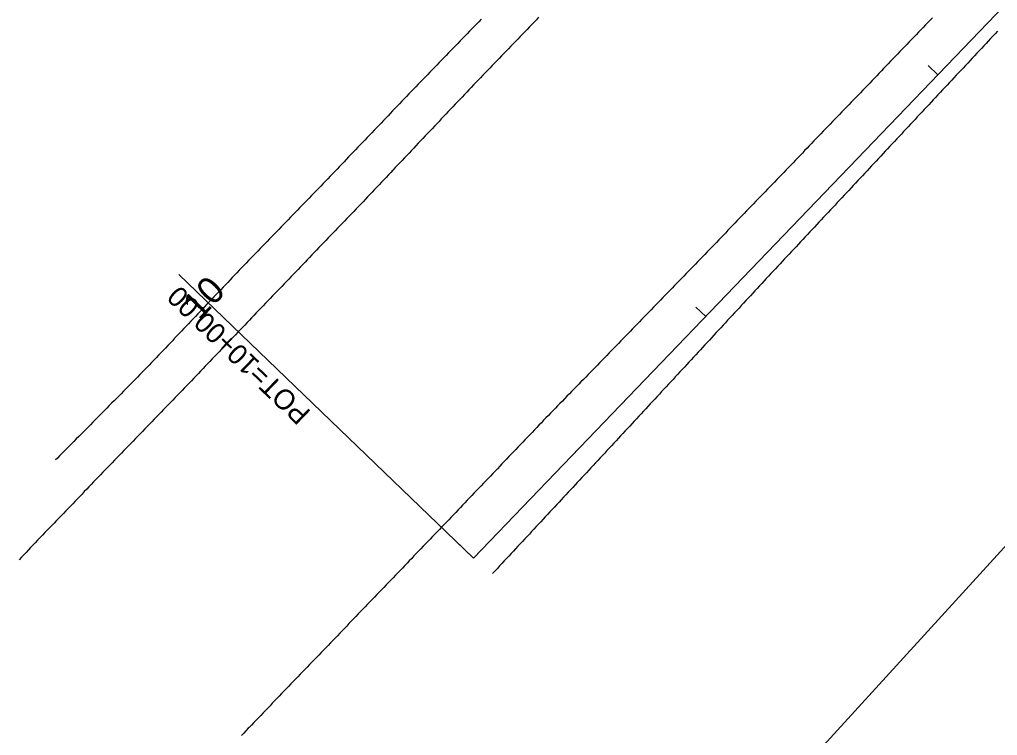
# Model space of a CAD drawing. Extents: x 205929 to 2357175, y -1785700 to 846739.
# Drawn here: x 2012822.1 to 2013114, y 820993.4 to 821206.9 of the extents above; entities that cross this region are included whole.
import ezdxf

# ---------------------------------------------------------------- set-up
doc = ezdxf.new("R2010")
doc.units = 0
for name, color, linetype in [('Default', 7, 'Continuous'), ('RD_EV_JTrib', 7, 'Continuous'), ('RD_HC_Cl', 7, 'Continuous'), ('RD_Sketch1', 7, 'Continuous')]:
    doc.layers.add(name, color=color, linetype=linetype)

# ---------------------------------------------------------------- blocks, each defined once
blk = doc.blocks.new('ARC0002L')
at = {"layer": 'Default'}
blk.add_lwpolyline([(-46.761, -51.417), (-19.138, -21.165), (-17.19, -18.199), (19.542, 20.689), (32.458, 32.041), (50.196, 48.051)], dxfattribs=at)

msp = doc.modelspace()

# ---------------------------------------------------------------- linework, layer by layer
at = {"layer": 'RD_HC_Cl'}
for p, q in [((2012957.62, 821046.27), (2013329.43, 821432.89)), ((2013096.25, 821190.43), (2013093.37, 821193.2)), ((2012957.62, 821046.27), (2012869.63, 821130.89)), ((2013026.94, 821118.35), (2013024.05, 821121.12)), ((2012957.62, 821046.27), (2012951.85, 821051.82))]:
    msp.add_line(p, q, dxfattribs=at)
at = {"layer": 'RD_Sketch1'}
for points in [[(2012977.08, 821207.59), (2012976.39, 821206.87), (2012975.7, 821206.14), (2012975, 821205.42), (2012974.31, 821204.7), (2012973.62, 821203.98), (2012972.92, 821203.26), (2012972.23, 821202.54), (2012971.54, 821201.82), (2012970.84, 821201.1), (2012970.15, 821200.38), (2012969.46, 821199.66), (2012968.76, 821198.94), (2012968.07, 821198.22), (2012967.38, 821197.5), (2012966.68, 821196.78), (2012965.99, 821196.06), (2012965.3, 821195.34), (2012964.6, 821194.61), (2012963.91, 821193.89), (2012963.22, 821193.17), (2012962.52, 821192.45), (2012961.83, 821191.73), (2012961.14, 821191.01), (2012960.44, 821190.29), (2012959.75, 821189.57), (2012959.06, 821188.85), (2012958.36, 821188.13), (2012957.67, 821187.41), (2012956.98, 821186.69), (2012956.28, 821185.97), (2012955.59, 821185.25), (2012954.9, 821184.53), (2012954.2, 821183.81), (2012953.51, 821183.08), (2012952.82, 821182.36), (2012952.14, 821181.63), (2012951.45, 821180.9), (2012950.76, 821180.18), (2012950.07, 821179.45), (2012949.39, 821178.72), (2012948.7, 821178), (2012948.01, 821177.27), (2012947.33, 821176.54), (2012946.64, 821175.82), (2012945.95, 821175.09), (2012945.27, 821174.36), (2012944.58, 821173.64), (2012943.89, 821172.91), (2012943.21, 821172.18), (2012942.52, 821171.46), (2012941.83, 821170.73), (2012941.15, 821170), (2012940.46, 821169.27), (2012939.77, 821168.55), (2012939.09, 821167.82), (2012938.4, 821167.09), (2012937.71, 821166.37), (2012937.03, 821165.64), (2012936.34, 821164.91), (2012935.65, 821164.19), (2012934.97, 821163.46), (2012934.28, 821162.73), (2012933.59, 821162.01), (2012932.91, 821161.28), (2012932.22, 821160.55), (2012931.53, 821159.83), (2012930.84, 821159.1), (2012930.16, 821158.37), (2012929.47, 821157.65), (2012928.78, 821156.92), (2012928.1, 821156.19), (2012927.41, 821155.46), (2012926.72, 821154.74), (2012926.03, 821154.01), (2012925.34, 821153.29), (2012924.65, 821152.57), (2012923.96, 821151.85), (2012923.26, 821151.13), (2012922.57, 821150.41), (2012921.88, 821149.69), (2012921.18, 821148.97), (2012920.49, 821148.24), (2012919.8, 821147.52), (2012919.11, 821146.8), (2012918.41, 821146.08), (2012917.72, 821145.36), (2012917.03, 821144.64), (2012916.34, 821143.92), (2012915.64, 821143.2), (2012914.95, 821142.48), (2012914.26, 821141.75), (2012913.56, 821141.03), (2012912.87, 821140.31), (2012912.18, 821139.59), (2012911.49, 821138.87), (2012910.79, 821138.15), (2012910.1, 821137.43), (2012909.41, 821136.71), (2012908.71, 821135.98), (2012908.02, 821135.26), (2012907.33, 821134.54), (2012906.64, 821133.82), (2012905.94, 821133.1), (2012905.25, 821132.38), (2012904.56, 821131.66), (2012903.87, 821130.94), (2012903.17, 821130.22), (2012902.48, 821129.49), (2012901.79, 821128.77), (2012901.09, 821128.05), (2012900.4, 821127.33), (2012899.71, 821126.61), (2012899.02, 821125.89), (2012898.32, 821125.17), (2012897.63, 821124.45), (2012896.94, 821123.72), (2012896.25, 821123), (2012895.56, 821122.28), (2012894.86, 821121.56), (2012894.17, 821120.84), (2012893.48, 821120.11), (2012892.79, 821119.39), (2012892.1, 821118.67), (2012891.4, 821117.95), (2012890.71, 821117.23), (2012890.02, 821116.5), (2012889.33, 821115.78), (2012888.64, 821115.06), (2012887.95, 821114.34), (2012887.25, 821113.62), (2012886.56, 821112.89), (2012885.87, 821112.17), (2012885.18, 821111.45), (2012884.49, 821110.73), (2012883.79, 821110.01), (2012883.1, 821109.28), (2012882.41, 821108.56), (2012881.72, 821107.84), (2012881.03, 821107.12), (2012880.33, 821106.4), (2012879.64, 821105.67), (2012878.95, 821104.95), (2012878.26, 821104.23), (2012877.57, 821103.51), (2012876.88, 821102.79), (2012876.18, 821102.06), (2012875.49, 821101.34), (2012874.8, 821100.62), (2012874.11, 821099.9), (2012873.42, 821099.18), (2012872.72, 821098.45), (2012872.03, 821097.73), (2012871.34, 821097.01), (2012870.65, 821096.29), (2012869.95, 821095.57), (2012869.26, 821094.85), (2012868.56, 821094.13), (2012867.87, 821093.41), (2012867.17, 821092.69), (2012866.48, 821091.98), (2012865.78, 821091.26), (2012865.09, 821090.54), (2012864.39, 821089.82), (2012863.7, 821089.1), (2012863, 821088.38), (2012862.31, 821087.66), (2012861.61, 821086.94), (2012860.91, 821086.22), (2012860.22, 821085.51), (2012859.52, 821084.79), (2012858.83, 821084.07), (2012858.13, 821083.35), (2012857.44, 821082.63), (2012856.74, 821081.91), (2012856.05, 821081.19), (2012855.35, 821080.47), (2012854.66, 821079.75), (2012853.96, 821079.04), (2012853.27, 821078.32), (2012852.57, 821077.6), (2012851.88, 821076.88), (2012851.18, 821076.16), (2012850.49, 821075.44), (2012849.79, 821074.72), (2012849.1, 821074), (2012848.4, 821073.28), (2012847.71, 821072.57), (2012847.01, 821071.85), (2012846.32, 821071.13), (2012845.62, 821070.41), (2012844.93, 821069.69), (2012844.23, 821068.97), (2012843.54, 821068.25), (2012842.84, 821067.53), (2012842.15, 821066.81), (2012841.45, 821066.09), (2012840.76, 821065.37), (2012840.07, 821064.65), (2012839.37, 821063.93), (2012838.68, 821063.21), (2012837.99, 821062.49), (2012837.29, 821061.77), (2012836.6, 821061.05), (2012835.9, 821060.33), (2012835.21, 821059.61), (2012834.52, 821058.89), (2012833.82, 821058.17), (2012833.13, 821057.45), (2012832.44, 821056.73), (2012831.74, 821056.01), (2012831.05, 821055.29), (2012830.35, 821054.57), (2012829.66, 821053.85), (2012828.97, 821053.13), (2012828.27, 821052.41), (2012828.18, 821052.32), (2012827.5, 821051.59), (2012826.81, 821050.86), (2012826.12, 821050.14), (2012825.43, 821049.41), (2012824.75, 821048.69), (2012824.06, 821047.96), (2012823.37, 821047.23), (2012822.68, 821046.51), (2012822, 821045.78)], [(2012959.88, 821207), (2012959.18, 821206.28), (2012958.48, 821205.56), (2012957.79, 821204.85), (2012957.09, 821204.13), (2012956.4, 821203.41), (2012955.7, 821202.69), (2012955.01, 821201.97), (2012954.31, 821201.25), (2012953.62, 821200.53), (2012952.92, 821199.81), (2012952.23, 821199.1), (2012951.53, 821198.38), (2012950.84, 821197.66), (2012950.14, 821196.94), (2012949.45, 821196.22), (2012948.75, 821195.5), (2012948.06, 821194.78), (2012947.36, 821194.06), (2012946.67, 821193.35), (2012945.97, 821192.63), (2012945.27, 821191.91), (2012944.58, 821191.19), (2012943.88, 821190.47), (2012943.19, 821189.75), (2012942.49, 821189.03), (2012941.8, 821188.31), (2012941.1, 821187.6), (2012940.41, 821186.88), (2012939.72, 821186.15), (2012939.03, 821185.43), (2012938.33, 821184.71), (2012937.64, 821183.99), (2012936.95, 821183.26), (2012936.26, 821182.54), (2012935.57, 821181.82), (2012934.88, 821181.1), (2012934.19, 821180.37), (2012933.49, 821179.65), (2012932.8, 821178.93), (2012932.11, 821178.21), (2012931.42, 821177.49), (2012930.73, 821176.76), (2012930.04, 821176.04), (2012929.34, 821175.32), (2012928.65, 821174.6), (2012927.96, 821173.87), (2012927.27, 821173.15), (2012926.58, 821172.43), (2012925.89, 821171.71), (2012925.2, 821170.98), (2012924.5, 821170.26), (2012923.81, 821169.54), (2012923.12, 821168.82), (2012922.43, 821168.09), (2012921.74, 821167.37), (2012921.05, 821166.65), (2012920.36, 821165.93), (2012919.66, 821165.2), (2012918.97, 821164.48), (2012918.28, 821163.76), (2012917.59, 821163.04), (2012916.9, 821162.31), (2012916.21, 821161.59), (2012915.52, 821160.87), (2012914.82, 821160.15), (2012914.13, 821159.42), (2012913.44, 821158.7), (2012912.75, 821157.98), (2012912.06, 821157.26), (2012911.36, 821156.54), (2012910.66, 821155.82), (2012909.97, 821155.11), (2012909.27, 821154.39), (2012908.58, 821153.67), (2012907.88, 821152.95), (2012907.18, 821152.23), (2012906.49, 821151.51), (2012905.79, 821150.8), (2012905.1, 821150.08), (2012904.4, 821149.36), (2012903.71, 821148.64), (2012903.01, 821147.92), (2012902.31, 821147.21), (2012901.62, 821146.49), (2012900.92, 821145.77), (2012900.23, 821145.05), (2012899.53, 821144.33), (2012898.84, 821143.61), (2012898.14, 821142.9), (2012897.44, 821142.18), (2012896.75, 821141.46), (2012896.05, 821140.74), (2012895.36, 821140.02), (2012894.66, 821139.3), (2012893.97, 821138.59), (2012893.27, 821137.87), (2012892.57, 821137.15), (2012891.88, 821136.43), (2012891.18, 821135.71), (2012890.49, 821134.99), (2012889.79, 821134.28), (2012889.09, 821133.56), (2012888.4, 821132.84), (2012887.7, 821132.12), (2012887.01, 821131.4), (2012886.32, 821130.68), (2012885.63, 821129.95), (2012884.94, 821129.23), (2012884.26, 821128.5), (2012883.57, 821127.78), (2012882.88, 821127.05), (2012882.19, 821126.33), (2012881.5, 821125.6), (2012880.81, 821124.88), (2012880.12, 821124.15), (2012879.43, 821123.43), (2012878.75, 821122.7), (2012878.06, 821121.98), (2012877.37, 821121.25), (2012876.68, 821120.53), (2012875.99, 821119.8), (2012875.3, 821119.08), (2012874.61, 821118.35), (2012873.92, 821117.63), (2012873.24, 821116.9), (2012872.55, 821116.18), (2012871.86, 821115.45), (2012871.17, 821114.73), (2012870.48, 821114), (2012869.79, 821113.28), (2012869.1, 821112.55), (2012868.41, 821111.83), (2012867.73, 821111.1), (2012867.04, 821110.38), (2012866.35, 821109.65), (2012865.66, 821108.93), (2012864.97, 821108.2), (2012864.28, 821107.48), (2012863.59, 821106.75), (2012862.9, 821106.03), (2012862.22, 821105.3), (2012861.53, 821104.58), (2012860.84, 821103.85), (2012860.15, 821103.13), (2012859.46, 821102.41), (2012858.75, 821101.7), (2012858.05, 821100.98), (2012857.35, 821100.27), (2012856.64, 821099.56), (2012855.94, 821098.85), (2012855.23, 821098.14), (2012854.53, 821097.43), (2012853.83, 821096.72), (2012853.12, 821096.01), (2012852.42, 821095.3), (2012851.72, 821094.59), (2012851.01, 821093.88), (2012850.31, 821093.17), (2012849.61, 821092.46), (2012848.9, 821091.74), (2012848.2, 821091.03), (2012847.5, 821090.32), (2012846.79, 821089.61), (2012846.09, 821088.9), (2012845.39, 821088.19), (2012844.68, 821087.48), (2012843.98, 821086.77), (2012843.28, 821086.06), (2012842.57, 821085.35), (2012841.87, 821084.64), (2012841.17, 821083.93), (2012840.46, 821083.22), (2012839.76, 821082.51), (2012839.05, 821081.79), (2012838.35, 821081.08), (2012837.65, 821080.37), (2012836.94, 821079.66), (2012836.24, 821078.95), (2012835.54, 821078.24), (2012834.83, 821077.53), (2012834.13, 821076.82), (2012833.43, 821076.11), (2012832.88, 821075.55)], [(2013094.62, 821207.45), (2013093.93, 821206.73), (2013093.23, 821206.01), (2013092.54, 821205.29), (2013091.85, 821204.56), (2013091.16, 821203.84), (2013090.47, 821203.12), (2013089.77, 821202.4), (2013089.08, 821201.68), (2013088.39, 821200.96), (2013087.7, 821200.23), (2013087.01, 821199.51), (2013086.31, 821198.79), (2013085.62, 821198.07), (2013084.93, 821197.35), (2013084.23, 821196.63), (2013083.54, 821195.91), (2013082.85, 821195.19), (2013082.15, 821194.47), (2013081.46, 821193.75), (2013080.77, 821193.03), (2013080.07, 821192.31), (2013079.38, 821191.59), (2013078.68, 821190.87), (2013077.99, 821190.15), (2013077.3, 821189.43), (2013076.6, 821188.71), (2013075.91, 821187.98), (2013075.22, 821187.26), (2013074.52, 821186.54), (2013073.83, 821185.82), (2013073.14, 821185.1), (2013072.44, 821184.38), (2013071.75, 821183.66), (2013071.06, 821182.94), (2013070.36, 821182.22), (2013069.67, 821181.5), (2013068.98, 821180.78), (2013068.28, 821180.06), (2013067.59, 821179.34), (2013066.9, 821178.62), (2013066.2, 821177.9), (2013065.51, 821177.18), (2013064.81, 821176.46), (2013064.12, 821175.74), (2013063.43, 821175.02), (2013062.73, 821174.3), (2013062.04, 821173.58), (2013061.35, 821172.86), (2013060.65, 821172.14), (2013059.96, 821171.42), (2013059.27, 821170.7), (2013058.57, 821169.97), (2013057.88, 821169.25), (2013057.19, 821168.53), (2013056.49, 821167.81), (2013055.8, 821167.09), (2013055.1, 821166.37), (2013054.41, 821165.65), (2013053.72, 821164.93), (2013053.02, 821164.21), (2013052.33, 821163.49), (2013051.64, 821162.77), (2013050.94, 821162.05), (2013050.25, 821161.33), (2013049.56, 821160.61), (2013048.86, 821159.89), (2013048.17, 821159.17), (2013047.48, 821158.45), (2013046.78, 821157.73), (2013046.09, 821157.01), (2013045.39, 821156.29), (2013044.7, 821155.57), (2013044.01, 821154.85), (2013043.31, 821154.13), (2013042.62, 821153.41), (2013041.93, 821152.69), (2013041.23, 821151.97), (2013040.54, 821151.25), (2013039.85, 821150.53), (2013039.15, 821149.81), (2013038.46, 821149.09), (2013037.76, 821148.37), (2013037.07, 821147.64), (2013036.38, 821146.92), (2013035.68, 821146.2), (2013034.99, 821145.48), (2013034.3, 821144.76), (2013033.6, 821144.04), (2013032.91, 821143.32), (2013032.22, 821142.6), (2013031.52, 821141.88), (2013030.83, 821141.16), (2013030.13, 821140.45), (2013029.43, 821139.73), (2013028.74, 821139.01), (2013028.04, 821138.29), (2013027.34, 821137.58), (2013026.65, 821136.86), (2013025.95, 821136.14), (2013025.25, 821135.42), (2013024.56, 821134.71), (2013023.86, 821133.99), (2013023.16, 821133.27), (2013022.47, 821132.55), (2013021.77, 821131.84), (2013021.07, 821131.12), (2013020.38, 821130.4), (2013019.68, 821129.68), (2013018.98, 821128.97), (2013018.29, 821128.25), (2013017.59, 821127.53), (2013016.89, 821126.81), (2013016.2, 821126.1), (2013015.5, 821125.38), (2013014.81, 821124.66), (2013014.11, 821123.95), (2013013.41, 821123.23), (2013012.72, 821122.51), (2013012.02, 821121.79), (2013011.32, 821121.08), (2013010.63, 821120.36), (2013009.93, 821119.64), (2013009.23, 821118.92), (2013008.54, 821118.21), (2013007.84, 821117.49), (2013007.14, 821116.77), (2013006.45, 821116.05), (2013005.75, 821115.34), (2013005.05, 821114.62), (2013004.36, 821113.9), (2013003.66, 821113.18), (2013002.96, 821112.47), (2013002.27, 821111.75), (2013001.57, 821111.03), (2013000.87, 821110.31), (2013000.18, 821109.6), (2012999.48, 821108.88), (2012998.78, 821108.16), (2012998.08, 821107.45), (2012997.39, 821106.73), (2012996.69, 821106.01), (2012995.99, 821105.29), (2012995.3, 821104.58), (2012994.6, 821103.86), (2012993.9, 821103.14), (2012993.21, 821102.43), (2012992.51, 821101.71), (2012991.81, 821100.99), (2012991.12, 821100.28), (2012990.42, 821099.56), (2012989.72, 821098.84), (2012989.03, 821098.12), (2012988.33, 821097.41), (2012987.63, 821096.69), (2012986.93, 821095.97), (2012986.24, 821095.26), (2012985.54, 821094.54), (2012984.84, 821093.82), (2012984.15, 821093.1), (2012983.45, 821092.39), (2012982.75, 821091.67), (2012982.06, 821090.95), (2012981.36, 821090.24), (2012980.66, 821089.52), (2012979.97, 821088.8), (2012979.27, 821088.08), (2012978.57, 821087.37), (2012977.88, 821086.65), (2012977.18, 821085.93), (2012976.49, 821085.21), (2012975.8, 821084.49), (2012975.11, 821083.76), (2012974.42, 821083.04), (2012973.73, 821082.32), (2012973.03, 821081.59), (2012972.34, 821080.87), (2012971.65, 821080.15), (2012970.96, 821079.42), (2012970.27, 821078.7), (2012969.58, 821077.98), (2012968.89, 821077.25), (2012968.2, 821076.53), (2012967.51, 821075.81), (2012966.82, 821075.08), (2012966.13, 821074.36), (2012965.44, 821073.64), (2012964.75, 821072.91), (2012964.06, 821072.19), (2012963.37, 821071.47), (2012962.68, 821070.74), (2012961.99, 821070.02), (2012961.3, 821069.3), (2012960.61, 821068.57), (2012959.92, 821067.85), (2012959.23, 821067.13), (2012958.54, 821066.4), (2012957.85, 821065.68), (2012957.15, 821064.96), (2012956.46, 821064.23), (2012955.77, 821063.51), (2012955.08, 821062.79), (2012954.39, 821062.06), (2012953.7, 821061.34), (2012953.01, 821060.62), (2012952.32, 821059.89), (2012951.63, 821059.17), (2012950.94, 821058.45), (2012950.25, 821057.72), (2012949.56, 821057), (2012948.86, 821056.28), (2012948.17, 821055.56), (2012947.48, 821054.84), (2012946.79, 821054.12), (2012946.09, 821053.4), (2012945.4, 821052.67), (2012944.71, 821051.95), (2012944.02, 821051.23), (2012943.32, 821050.51), (2012942.63, 821049.79), (2012941.94, 821049.07), (2012941.24, 821048.35), (2012940.55, 821047.63), (2012939.86, 821046.91), (2012939.17, 821046.18), (2012938.47, 821045.46), (2012937.78, 821044.74), (2012937.09, 821044.02), (2012936.4, 821043.3), (2012935.7, 821042.58), (2012935.01, 821041.86), (2012934.32, 821041.14), (2012933.62, 821040.41), (2012932.93, 821039.69), (2012932.24, 821038.97), (2012931.55, 821038.25), (2012930.85, 821037.53), (2012930.16, 821036.81), (2012929.47, 821036.09), (2012928.78, 821035.37), (2012928.08, 821034.65), (2012927.39, 821033.92), (2012926.7, 821033.2), (2012926.01, 821032.48), (2012925.31, 821031.76), (2012924.62, 821031.04), (2012923.93, 821030.32), (2012923.23, 821029.6), (2012922.54, 821028.88), (2012921.85, 821028.16), (2012921.15, 821027.44), (2012920.46, 821026.72), (2012919.77, 821025.99), (2012919.07, 821025.27), (2012918.38, 821024.55), (2012917.69, 821023.83), (2012916.99, 821023.11), (2012916.3, 821022.39), (2012915.61, 821021.67), (2012914.91, 821020.95), (2012914.22, 821020.23), (2012913.53, 821019.51), (2012912.83, 821018.79), (2012912.14, 821018.07), (2012911.44, 821017.35), (2012910.75, 821016.63), (2012910.06, 821015.91), (2012909.36, 821015.19), (2012908.67, 821014.47), (2012907.98, 821013.75), (2012907.28, 821013.03), (2012906.59, 821012.31), (2012905.9, 821011.59), (2012905.2, 821010.87), (2012904.51, 821010.15), (2012903.82, 821009.43), (2012903.12, 821008.71), (2012902.43, 821007.99), (2012901.73, 821007.27), (2012901.04, 821006.55), (2012900.35, 821005.83), (2012899.65, 821005.11), (2012898.96, 821004.39), (2012898.27, 821003.67), (2012897.57, 821002.94), (2012896.88, 821002.22), (2012896.19, 821001.5), (2012895.49, 821000.78), (2012894.8, 821000.06), (2012894.11, 820999.34), (2012893.41, 820998.62), (2012892.72, 820997.9), (2012892.02, 820997.18), (2012891.33, 820996.46), (2012890.64, 820995.74), (2012890.39, 820995.48), (2012889.7, 820994.76), (2012889.02, 820994.03), (2012888.33, 820993.3)], [(2013114.06, 821203.4), (2013113.38, 821202.67), (2013112.69, 821201.94), (2013112.01, 821201.22), (2013112.01, 821201.22), (2013111.32, 821200.49), (2013110.64, 821199.76), (2013109.95, 821199.03), (2013109.27, 821198.3), (2013108.59, 821197.57), (2013107.9, 821196.84), (2013107.22, 821196.11), (2013106.53, 821195.38), (2013105.85, 821194.65), (2013105.16, 821193.92), (2013104.48, 821193.19), (2013103.8, 821192.46), (2013103.11, 821191.74), (2013102.43, 821191.01), (2013101.74, 821190.28), (2013101.06, 821189.55), (2013100.38, 821188.82), (2013099.69, 821188.09), (2013099.01, 821187.36), (2013098.32, 821186.63), (2013097.64, 821185.9), (2013096.95, 821185.17), (2013096.27, 821184.44), (2013095.59, 821183.71), (2013094.9, 821182.98), (2013094.22, 821182.25), (2013093.54, 821181.52), (2013092.85, 821180.79), (2013092.17, 821180.06), (2013091.49, 821179.33), (2013090.81, 821178.6), (2013090.12, 821177.87), (2013089.44, 821177.14), (2013088.76, 821176.41), (2013088.08, 821175.68), (2013087.39, 821174.94), (2013086.71, 821174.21), (2013086.03, 821173.48), (2013085.35, 821172.75), (2013084.66, 821172.02), (2013083.98, 821171.29), (2013083.3, 821170.56), (2013082.62, 821169.83), (2013081.93, 821169.1), (2013081.25, 821168.37), (2013080.57, 821167.64), (2013079.89, 821166.91), (2013079.2, 821166.17), (2013078.52, 821165.44), (2013077.84, 821164.71), (2013077.16, 821163.98), (2013076.47, 821163.25), (2013075.79, 821162.52), (2013075.11, 821161.79), (2013074.43, 821161.06), (2013073.74, 821160.33), (2013073.06, 821159.6), (2013072.38, 821158.87), (2013071.7, 821158.14), (2013071.01, 821157.4), (2013070.33, 821156.67), (2013069.65, 821155.95), (2013068.96, 821155.22), (2013068.28, 821154.49), (2013068.28, 821154.49), (2013067.6, 821153.76), (2013066.91, 821153.03), (2013066.23, 821152.3), (2013065.55, 821151.57), (2013064.86, 821150.84), (2013064.18, 821150.11), (2013063.49, 821149.38), (2013062.81, 821148.65), (2013062.13, 821147.92), (2013061.44, 821147.19), (2013060.76, 821146.46), (2013060.08, 821145.73), (2013059.39, 821145), (2013058.71, 821144.27), (2013058.02, 821143.54), (2013057.34, 821142.81), (2013056.66, 821142.08), (2013055.97, 821141.35), (2013055.29, 821140.62), (2013054.61, 821139.89), (2013053.92, 821139.16), (2013053.24, 821138.43), (2013052.55, 821137.7), (2013051.87, 821136.97), (2013051.19, 821136.24), (2013050.5, 821135.51), (2013049.82, 821134.78), (2013049.14, 821134.05), (2013048.45, 821133.32), (2013047.77, 821132.59), (2013047.08, 821131.86), (2013046.4, 821131.13), (2013045.72, 821130.4), (2013045.04, 821129.67), (2013044.36, 821128.93), (2013043.68, 821128.2), (2013043, 821127.47), (2013042.32, 821126.73), (2013041.65, 821126), (2013040.97, 821125.26), (2013040.29, 821124.53), (2013039.61, 821123.8), (2013038.93, 821123.06), (2013038.25, 821122.33), (2013037.57, 821121.59), (2013036.89, 821120.86), (2013036.21, 821120.13), (2013035.53, 821119.39), (2013034.85, 821118.66), (2013034.18, 821117.92), (2013033.5, 821117.19), (2013032.82, 821116.46), (2013032.14, 821115.72), (2013031.46, 821114.99), (2013030.78, 821114.25), (2013030.1, 821113.52), (2013029.42, 821112.79), (2013028.74, 821112.05), (2013028.06, 821111.32), (2013027.38, 821110.58), (2013026.7, 821109.85), (2013026.03, 821109.12), (2013025.35, 821108.38), (2013024.67, 821107.65), (2013024.67, 821107.65), (2013023.99, 821106.91), (2013023.31, 821106.18), (2013022.63, 821105.45), (2013021.95, 821104.71), (2013021.27, 821103.98), (2013020.59, 821103.24), (2013019.91, 821102.51), (2013019.23, 821101.78), (2013018.55, 821101.04), (2013017.87, 821100.31), (2013017.19, 821099.58), (2013016.51, 821098.84), (2013015.83, 821098.11), (2013015.15, 821097.38), (2013014.47, 821096.65), (2013013.79, 821095.91), (2013013.11, 821095.18), (2013012.43, 821094.45), (2013011.75, 821093.71), (2013011.07, 821092.98), (2013010.39, 821092.25), (2013009.71, 821091.52), (2013009.03, 821090.78), (2013008.35, 821090.05), (2013007.67, 821089.32), (2013006.99, 821088.58), (2013006.31, 821087.85), (2013005.63, 821087.12), (2013004.95, 821086.39), (2013004.27, 821085.65), (2013003.59, 821084.92), (2013002.91, 821084.19), (2013002.23, 821083.45), (2013001.55, 821082.72), (2013000.87, 821081.99), (2013000.19, 821081.26), (2012999.51, 821080.52), (2012998.83, 821079.79), (2012998.15, 821079.06), (2012997.47, 821078.32), (2012996.79, 821077.59), (2012996.11, 821076.86), (2012995.43, 821076.13), (2012994.75, 821075.39), (2012994.06, 821074.66), (2012993.38, 821073.93), (2012992.7, 821073.19), (2012992.02, 821072.46), (2012991.34, 821071.73), (2012990.66, 821071), (2012989.98, 821070.27), (2012989.3, 821069.53), (2012988.62, 821068.8), (2012987.93, 821068.07), (2012987.25, 821067.34), (2012986.57, 821066.61), (2012985.89, 821065.88), (2012985.21, 821065.15), (2012984.52, 821064.41), (2012983.84, 821063.68), (2012983.16, 821062.95), (2012982.48, 821062.22), (2012981.8, 821061.49), (2012981.12, 821060.76), (2012981.12, 821060.76), (2012980.43, 821060.03), (2012979.75, 821059.29), (2012979.07, 821058.56), (2012978.39, 821057.83), (2012977.71, 821057.1), (2012977.02, 821056.37), (2012976.34, 821055.64), (2012975.66, 821054.91), (2012974.98, 821054.17), (2012974.3, 821053.44), (2012973.61, 821052.71), (2012972.93, 821051.98), (2012972.25, 821051.25), (2012971.57, 821050.52), (2012970.89, 821049.79), (2012970.2, 821049.05), (2012969.52, 821048.32), (2012968.84, 821047.59), (2012968.16, 821046.86), (2012967.48, 821046.13), (2012966.8, 821045.4), (2012966.11, 821044.67), (2012965.43, 821043.93), (2012964.75, 821043.2), (2012964.07, 821042.47), (2012963.39, 821041.74), (2012963.32, 821041.67)]]:
    msp.add_lwpolyline(points, dxfattribs=at)

# ---------------------------------------------------------------- block references
at = {"layer": 'RD_EV_JTrib', "xscale": 3.937007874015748, "yscale": 3.937007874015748}
msp.add_blockref('ARC0002L', (2013204.83, 821147.45), dxfattribs=at)

# ---------------------------------------------------------------- texts
at = {"layer": 'RD_HC_Cl'}
for s, height, rotation, p in [('10', 8, 46.1187, (2012875.76, 821116.96)), ('POT=10+00.00', 6, 136.1187, (2012909.38, 821089.89))]:
    msp.add_text(s, height=height, rotation=rotation, dxfattribs=at).set_placement(p)

doc.saveas('drawing.dxf')
